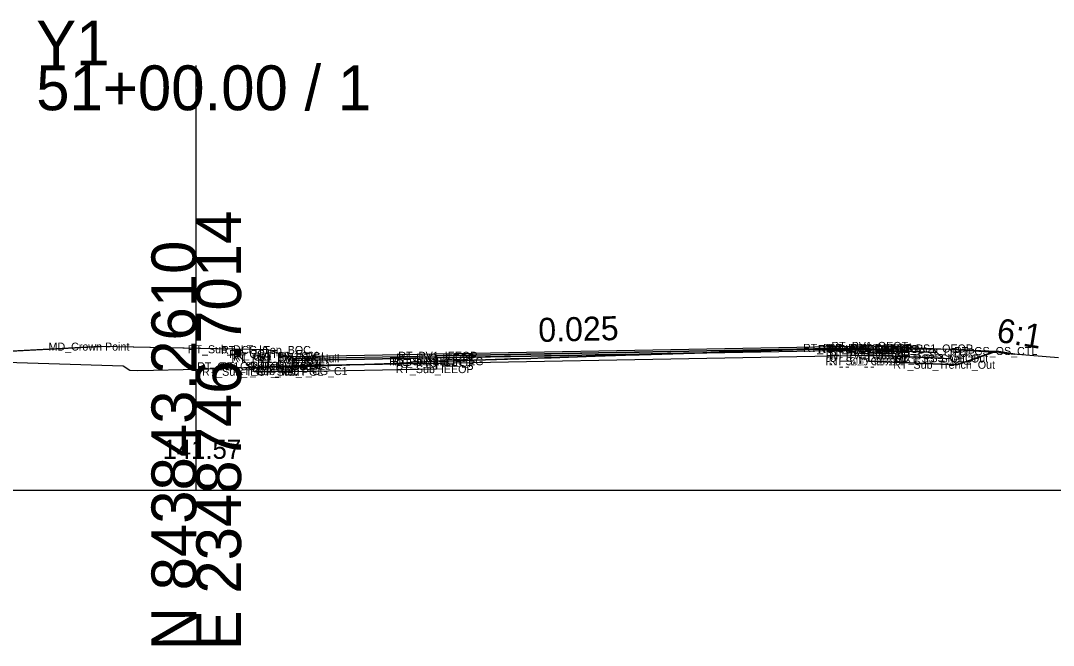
# Model space of a CAD drawing. Extents: x -26 to 2349090, y -10 to 844481.
# Drawn here: x 1139 to 1203.5, y 16490.3 to 16529.4 of the extents above; entities that cross this region are included whole.
import ezdxf

# ---------------------------------------------------------------- set-up
doc = ezdxf.new("R2010")
doc.units = 0
for name, color, linetype in [('Exist CMT Pavement', 7, 'Continuous'), ('Exist Cross Section Cell', 7, 'Continuous'), ('Exist XS Center Line Elevation Label', 7, 'Continuous'), ('Exist XS Ground Line', 7, 'Continuous'), ('Prop CMT Conc Surface', 7, 'Continuous'), ('Prop CMT Concrete Structures', 7, 'Continuous'), ('Prop CMT Pvmt Course 1', 7, 'Continuous'), ('Prop CMT Pvmt Course 1 CG', 7, 'Continuous'), ('Prop CMT Pvmt Course 1 Wedge', 7, 'Continuous'), ('Prop CMT Pvmt Course 2', 7, 'Continuous'), ('Prop CMT Pvmt Course 2 Wedge', 7, 'Continuous'), ('Prop CMT Pvmt Course 3', 7, 'Continuous'), ('Prop CMT Pvmt Surface', 7, 'Continuous'), ('Prop CMT Pvmt Surface Shoulder', 7, 'Continuous'), ('Prop CMT Pvmt Wedge Surface 1', 7, 'Continuous'), ('Prop CMT Pvmt Wedge Surface 2', 7, 'Continuous'), ('Prop CMT Pvmt Wedge Surface 3', 7, 'Continuous'), ('Prop CMT Shld Paved Course 1', 7, 'Continuous'), ('Prop CMT Shld Paved Course 2', 7, 'Continuous'), ('Prop CMT Shld Paved Course 3', 7, 'Continuous'), ('Prop CMT Slope Grass', 7, 'Continuous'), ('Prop CMT Subgrade Earthwork', 7, 'Continuous'), ('Prop XS Earthwork Shape', 7, 'Continuous'), ('Prop XS SE Text', 7, 'Continuous'), ('Prop XS Side Slope Text', 7, 'Continuous'), ('Scratch_Level_0', 7, 'Continuous')]:
    doc.layers.add(name, color=color, linetype=linetype)

msp = doc.modelspace()

# ---------------------------------------------------------------- linework, layer by layer
at = {"layer": 'Exist CMT Pavement'}
for p, q in [((1177.67, 16508.472), (1178.41, 16508.495)), ((1178.41, 16508.495), (1180.424, 16508.555)), ((1180.424, 16508.555), (1182.664, 16508.632)), ((1182.664, 16508.632), (1183.153, 16508.649)), ((1183.153, 16508.649), (1184.902, 16508.704)), ((1184.902, 16508.704), (1185.911, 16508.745)), ((1185.911, 16508.745), (1188.624, 16508.816)), ((1188.624, 16508.816), (1188.663, 16508.816)), ((1188.663, 16508.816), (1188.681, 16508.817)), ((1188.681, 16508.817), (1190.556, 16508.826)), ((1190.556, 16508.826), (1191.441, 16508.832)), ((1191.441, 16508.832), (1191.998, 16508.834)), ((1165.001, 16508.067), (1166.108, 16508.103)), ((1166.108, 16508.103), (1166.62, 16508.117)), ((1166.62, 16508.117), (1168.07, 16508.161)), ((1168.07, 16508.161), (1169.243, 16508.198)), ((1169.243, 16508.198), (1169.448, 16508.203)), ((1169.448, 16508.203), (1169.629, 16508.211)), ((1169.629, 16508.211), (1170.889, 16508.247)), ((1170.889, 16508.247), (1171.757, 16508.272)), ((1171.757, 16508.272), (1172.159, 16508.284)), ((1172.159, 16508.284), (1173.259, 16508.325)), ((1173.259, 16508.325), (1174.922, 16508.383)), ((1174.922, 16508.383), (1176.816, 16508.446)), ((1176.816, 16508.446), (1177.67, 16508.472))]:
    msp.add_line(p, q, dxfattribs=at)
at = {"layer": 'Exist Cross Section Cell'}
for p, q in [((1150, 16500), (1150, 16526.561)), ((1000, 16500), (1150, 16500)), ((1150, 16500), (1300, 16500))]:
    msp.add_line(p, q, dxfattribs=at)
at = {"layer": 'Exist XS Ground Line'}
msp.add_lwpolyline([(1135.459, 16508.084), (1145.443, 16507.772), (1145.852, 16507.511), (1146.316, 16507.489), (1147.334, 16507.506), (1149.183, 16507.543), (1150.096, 16507.57), (1153.053, 16507.671), (1155.6, 16507.728), (1156.437, 16507.748), (1157.536, 16507.771), (1158.394, 16507.801), (1159.082, 16507.827), (1161.125, 16507.905), (1162.341, 16507.955), (1163.894, 16508.029), (1164.221, 16508.042), (1164.965, 16508.066), (1166.108, 16508.103), (1166.62, 16508.117), (1168.07, 16508.161), (1169.448, 16508.203), (1170.889, 16508.247), (1171.757, 16508.272), (1172.159, 16508.284), (1173.258, 16508.325), (1174.922, 16508.383), (1176.816, 16508.446), (1177.67, 16508.472), (1178.41, 16508.495), (1180.424, 16508.555), (1182.664, 16508.632), (1183.153, 16508.649), (1184.902, 16508.704), (1185.911, 16508.745), (1188.681, 16508.817), (1190.556, 16508.826), (1191.441, 16508.832), (1193.129, 16508.839), (1193.505, 16508.84), (1194.047, 16508.852), (1194.533, 16508.854), (1197.341, 16508.818), (1200.031, 16508.605), (1203.856, 16508.303)], dxfattribs=at)
at = {"layer": 'Prop CMT Conc Surface'}
for p, q in [((1155.249, 16508.523), (1154.49, 16508.773)), ((1155.25, 16508.356), (1155.249, 16508.523)), ((1156, 16508.37), (1155.25, 16508.356))]:
    msp.add_line(p, q, dxfattribs=at)
at = {"layer": 'Prop CMT Concrete Structures'}
for p, q in [((1155.249, 16508.523), (1154.49, 16508.773)), ((1154.49, 16508.773), (1154.49, 16507.759)), ((1155.25, 16508.356), (1155.249, 16508.523)), ((1156, 16508.37), (1155.25, 16508.356)), ((1156, 16507.787), (1156, 16508.37)), ((1154.49, 16507.759), (1156, 16507.787))]:
    msp.add_line(p, q, dxfattribs=at)
at = {"layer": 'Prop CMT Pvmt Course 1'}
for p, q in [((1156, 16508.37), (1192, 16509.027)), ((1192, 16508.902), (1165, 16508.409)), ((1192, 16509.027), (1192, 16508.777)), ((1192, 16508.777), (1192, 16508.902)), ((1192, 16508.777), (1192, 16508.777)), ((1156, 16508.12), (1156, 16508.37)), ((1165, 16508.284), (1156, 16508.12)), ((1165, 16508.409), (1165, 16508.284))]:
    msp.add_line(p, q, dxfattribs=at)
at = {"layer": 'Prop CMT Pvmt Course 1 CG'}
for p, q in [((1153.99, 16507.75), (1153.65, 16507.41)), ((1153.65, 16507.41), (1156, 16507.453)), ((1156, 16507.787), (1153.99, 16507.75)), ((1156, 16507.453), (1156, 16507.787))]:
    msp.add_line(p, q, dxfattribs=at)
at = {"layer": 'Prop CMT Pvmt Course 1 Wedge'}
for p, q in [((1169.243, 16508.487), (1169.448, 16508.491)), ((1169.448, 16508.491), (1169.629, 16508.494)), ((1169.629, 16508.494), (1170.889, 16508.517)), ((1170.889, 16508.517), (1171.757, 16508.533)), ((1171.757, 16508.533), (1172.159, 16508.54)), ((1172.159, 16508.54), (1173.259, 16508.56)), ((1173.259, 16508.56), (1174.922, 16508.591)), ((1174.922, 16508.591), (1176.816, 16508.625)), ((1176.816, 16508.5), (1174.922, 16508.466)), ((1176.816, 16508.625), (1177.67, 16508.641)), ((1177.67, 16508.516), (1176.816, 16508.5)), ((1177.67, 16508.641), (1178.41, 16508.654)), ((1178.41, 16508.529), (1177.67, 16508.516)), ((1178.41, 16508.654), (1180.424, 16508.691)), ((1180.424, 16508.566), (1178.41, 16508.529)), ((1180.424, 16508.691), (1182.664, 16508.732)), ((1181.115, 16508.579), (1180.424, 16508.566)), ((1182.664, 16508.632), (1181.115, 16508.579)), ((1182.664, 16508.732), (1183.153, 16508.741)), ((1183.153, 16508.649), (1182.664, 16508.632)), ((1183.153, 16508.741), (1184.902, 16508.773)), ((1184.902, 16508.704), (1183.153, 16508.649)), ((1184.902, 16508.773), (1185.911, 16508.791)), ((1185.911, 16508.745), (1184.902, 16508.704)), ((1185.911, 16508.791), (1188.624, 16508.841)), ((1188.624, 16508.816), (1185.911, 16508.745)), ((1188.624, 16508.841), (1188.663, 16508.841)), ((1188.663, 16508.816), (1188.624, 16508.816)), ((1188.663, 16508.841), (1188.681, 16508.842)), ((1188.681, 16508.817), (1188.663, 16508.816)), ((1188.681, 16508.842), (1190.556, 16508.876)), ((1190.556, 16508.826), (1188.681, 16508.817)), ((1190.556, 16508.876), (1191.441, 16508.892)), ((1191.441, 16508.832), (1190.556, 16508.826)), ((1191.441, 16508.892), (1192, 16508.902)), ((1192, 16508.834), (1191.441, 16508.832)), ((1192, 16508.902), (1192, 16508.834)), ((1165, 16508.409), (1166.108, 16508.43)), ((1165, 16508.284), (1165, 16508.409)), ((1166.108, 16508.305), (1165, 16508.284)), ((1166.108, 16508.43), (1166.62, 16508.439)), ((1166.62, 16508.314), (1166.108, 16508.305)), ((1166.62, 16508.439), (1168.07, 16508.465)), ((1168.07, 16508.34), (1166.62, 16508.314)), ((1168.07, 16508.465), (1169.243, 16508.487)), ((1169.243, 16508.362), (1168.07, 16508.34)), ((1169.448, 16508.366), (1169.243, 16508.362)), ((1169.629, 16508.369), (1169.448, 16508.366)), ((1170.889, 16508.392), (1169.629, 16508.369)), ((1171.757, 16508.408), (1170.889, 16508.392)), ((1172.159, 16508.415), (1171.757, 16508.408)), ((1173.259, 16508.435), (1172.159, 16508.415)), ((1174.922, 16508.466), (1173.259, 16508.435))]:
    msp.add_line(p, q, dxfattribs=at)
at = {"layer": 'Prop CMT Pvmt Course 2'}
for p, q in [((1192, 16508.444), (1192, 16508.777)), ((1192, 16508.777), (1192, 16508.777)), ((1192, 16508.777), (1192, 16508.444)), ((1156, 16508.12), (1165, 16508.284)), ((1156, 16507.787), (1156, 16508.12)), ((1165, 16507.951), (1156, 16507.787)), ((1165, 16508.284), (1165, 16507.951)), ((1192, 16508.444), (1192, 16508.444))]:
    msp.add_line(p, q, dxfattribs=at)
at = {"layer": 'Prop CMT Pvmt Course 2 Wedge'}
for p, q in [((1174.922, 16508.466), (1176.816, 16508.5)), ((1176.816, 16508.5), (1177.67, 16508.516)), ((1177.67, 16508.516), (1178.41, 16508.529)), ((1178.41, 16508.495), (1177.67, 16508.472)), ((1178.41, 16508.529), (1180.424, 16508.566)), ((1180.424, 16508.555), (1178.41, 16508.495)), ((1180.424, 16508.566), (1181.115, 16508.579)), ((1181.115, 16508.579), (1180.424, 16508.555)), ((1165, 16508.284), (1166.108, 16508.305)), ((1165, 16508.067), (1165, 16508.284)), ((1166.108, 16508.103), (1165, 16508.067)), ((1166.108, 16508.305), (1166.62, 16508.314)), ((1166.62, 16508.117), (1166.108, 16508.103)), ((1166.62, 16508.314), (1168.07, 16508.34)), ((1168.07, 16508.161), (1166.62, 16508.117)), ((1168.07, 16508.34), (1169.243, 16508.362)), ((1169.243, 16508.198), (1168.07, 16508.161)), ((1169.243, 16508.362), (1169.448, 16508.366)), ((1169.448, 16508.203), (1169.243, 16508.198)), ((1169.448, 16508.366), (1169.629, 16508.369)), ((1169.629, 16508.211), (1169.448, 16508.203)), ((1169.629, 16508.369), (1170.889, 16508.392)), ((1170.889, 16508.247), (1169.629, 16508.211)), ((1170.889, 16508.392), (1171.757, 16508.408)), ((1171.757, 16508.272), (1170.889, 16508.247)), ((1171.757, 16508.408), (1172.159, 16508.415)), ((1172.159, 16508.284), (1171.757, 16508.272)), ((1172.159, 16508.415), (1173.259, 16508.435)), ((1173.259, 16508.325), (1172.159, 16508.284)), ((1173.259, 16508.435), (1174.922, 16508.466)), ((1174.922, 16508.383), (1173.259, 16508.325)), ((1176.816, 16508.446), (1174.922, 16508.383)), ((1177.67, 16508.472), (1176.816, 16508.446))]:
    msp.add_line(p, q, dxfattribs=at)
at = {"layer": 'Prop CMT Pvmt Course 3'}
for p, q in [((1156, 16507.787), (1165, 16507.951)), ((1165, 16507.951), (1165, 16507.576)), ((1192, 16508.444), (1192, 16508.444)), ((1192, 16508.444), (1192, 16508.069)), ((1192, 16508.069), (1192, 16508.444)), ((1192, 16508.069), (1192, 16508.069)), ((1156, 16507.412), (1156, 16507.787)), ((1165, 16507.576), (1156, 16507.412))]:
    msp.add_line(p, q, dxfattribs=at)
at = {"layer": 'Prop CMT Pvmt Surface'}
msp.add_line((1156, 16508.37), (1192, 16509.027), dxfattribs=at)
at = {"layer": 'Prop CMT Pvmt Surface Shoulder'}
msp.add_line((1192, 16509.027), (1196, 16508.867), dxfattribs=at)
at = {"layer": 'Prop CMT Pvmt Wedge Surface 1'}
for p, q in [((1165, 16508.409), (1192, 16508.902)), ((1192, 16508.902), (1192, 16509.027)), ((1192, 16508.902), (1192, 16508.902)), ((1156, 16508.245), (1165, 16508.409)), ((1156, 16508.37), (1156, 16508.245))]:
    msp.add_line(p, q, dxfattribs=at)
at = {"layer": 'Prop CMT Pvmt Wedge Surface 2'}
for p, q in [((1156, 16508.12), (1192, 16508.777)), ((1192, 16508.777), (1192, 16509.027)), ((1156, 16508.37), (1156, 16508.12))]:
    msp.add_line(p, q, dxfattribs=at)
at = {"layer": 'Prop CMT Pvmt Wedge Surface 3'}
for p, q in [((1192, 16508.444), (1192, 16509.027)), ((1156, 16507.787), (1192, 16508.444)), ((1156, 16508.37), (1156, 16507.787))]:
    msp.add_line(p, q, dxfattribs=at)
at = {"layer": 'Prop CMT Shld Paved Course 1'}
for p, q in [((1155.249, 16508.523), (1155.25, 16508.356)), ((1192, 16509.027), (1196, 16508.867)), ((1192, 16508.777), (1192, 16509.027)), ((1196.26, 16508.607), (1192, 16508.777)), ((1196, 16508.867), (1196.26, 16508.607))]:
    msp.add_line(p, q, dxfattribs=at)
at = {"layer": 'Prop CMT Shld Paved Course 2'}
for p, q in [((1192, 16508.777), (1196.26, 16508.607)), ((1192, 16508.444), (1192, 16508.777)), ((1196.26, 16508.607), (1196.608, 16508.26)), ((1196.608, 16508.26), (1192, 16508.444))]:
    msp.add_line(p, q, dxfattribs=at)
at = {"layer": 'Prop CMT Shld Paved Course 3'}
for p, q in [((1192, 16508.444), (1196.608, 16508.26)), ((1192, 16508.069), (1192, 16508.444)), ((1197.498, 16507.849), (1192, 16508.069)), ((1196.608, 16508.26), (1197.108, 16508.24)), ((1197.108, 16508.24), (1197.498, 16507.849))]:
    msp.add_line(p, q, dxfattribs=at)
at = {"layer": 'Prop CMT Slope Grass'}
for p, q in [((1133.51, 16508.441), (1144, 16508.983)), ((1154.49, 16508.773), (1144, 16508.983)), ((1196, 16508.867), (1200, 16508.707)), ((1200, 16508.707), (1201.14, 16508.517))]:
    msp.add_line(p, q, dxfattribs=at)
at = {"layer": 'Prop CMT Subgrade Earthwork'}
for p, q in [((1152.243, 16508.818), (1153.65, 16507.41)), ((1192, 16508.069), (1191.998, 16508.834)), ((1197.498, 16507.849), (1200, 16508.707)), ((1165, 16507.576), (1165.001, 16508.067)), ((1192, 16508.069), (1197.498, 16507.849)), ((1192, 16508.069), (1192, 16508.069)), ((1156, 16507.453), (1153.65, 16507.41)), ((1165, 16507.576), (1156, 16507.412)), ((1156, 16507.412), (1156, 16507.453))]:
    msp.add_line(p, q, dxfattribs=at)
at = {"layer": 'Prop XS Earthwork Shape'}
for points in [[(1146.316, 16507.489), (1147.334, 16507.506), (1149.183, 16507.543), (1150.096, 16507.57), (1153.053, 16507.671), (1153.383, 16507.678), (1152.243, 16508.818), (1144, 16508.983), (1135.67, 16508.553), (1135.209, 16508.092), (1135.459, 16508.084), (1145.443, 16507.772), (1145.852, 16507.511)], [(1191.998, 16508.834), (1193.129, 16508.839), (1193.505, 16508.84), (1194.047, 16508.852), (1194.533, 16508.854), (1197.202, 16508.819), (1197.439, 16508.81), (1199.763, 16508.626), (1197.498, 16507.849), (1192, 16508.069)], [(1197.341, 16508.818), (1197.439, 16508.81), (1197.202, 16508.819)], [(1200.031, 16508.605), (1201.14, 16508.517), (1200, 16508.707), (1199.763, 16508.626)], [(1163.894, 16508.029), (1164.221, 16508.042), (1164.965, 16508.066), (1165.001, 16508.067), (1165, 16507.576), (1156, 16507.412), (1156, 16507.453), (1153.65, 16507.41), (1153.383, 16507.678), (1155.6, 16507.728), (1156.437, 16507.748), (1157.536, 16507.771), (1158.394, 16507.801), (1159.082, 16507.827), (1161.125, 16507.905), (1162.341, 16507.955)], [(1169.243, 16508.198), (1169.448, 16508.203), (1168.07, 16508.161)], [(1169.629, 16508.211), (1170.889, 16508.247), (1169.448, 16508.203)]]:
    msp.add_lwpolyline(points, close=True, dxfattribs=at)

# ---------------------------------------------------------------- texts
at = {"layer": 'Exist Cross Section Cell'}
for s, p in [('Y1', (1140, 16526.561)), ('51+00.00 / 1', (1140, 16523.761))]:
    msp.add_text(s, height=2.8, dxfattribs=at).set_placement(p)
for s, p in [('E 2348746.7014', (1152.8, 16490)), ('N 843843.2610', (1150, 16490))]:
    msp.add_text(s, height=2.8, rotation=90, dxfattribs=at).set_placement(p)
at = {"layer": 'Exist XS Center Line Elevation Label'}
msp.add_text('141.57', height=1.2, dxfattribs=at).set_placement((1147.893, 16501.967))
at = {"layer": 'Prop XS SE Text'}
msp.add_text('0.025', height=1.5, rotation=1.4321, dxfattribs=at).set_placement((1171.38, 16509.271))
at = {"layer": 'Prop XS Side Slope Text'}
msp.add_text('6:1', height=1.5, rotation=350.53768, dxfattribs=at).set_placement((1199.932, 16509.301))
at = {"layer": 'Scratch_Level_0'}
for s, p in [('MD_Crown Point', (1140.768, 16508.733)), ('RT_PV1_OEOT_Overlay', (1187.898, 16508.652)), ('RT_PV1_OEEOP', (1189.457, 16508.652)), ('RT_PV1_OEOT', (1189.673, 16508.777)), ('RT_Sub_DLT_In', (1149.467, 16508.568)), ('RT_CG_Top_BOC', (1151.549, 16508.523)), ('RT_CG_Top_Face', (1152.052, 16508.273)), ('RT_PV1_Overlay_Null', (1152.205, 16507.995)), ('RT_CG_Top_Gut', (1152.297, 16508.106)), ('RT_PV1_PGL', (1153.933, 16508.12)), ('RT_PV2_IEEOP', (1162.476, 16508.034)), ('RT_PV1_IEEOP', (1162.618, 16508.159)), ('RT_Sub Tie Out', (1188.821, 16508.584)), ('RT_PV_OEEOP_EG', (1188.872, 16508.584)), ('RT_PV2_OEEOP', (1189.315, 16508.527)), ('RT_PV3_OEEOP', (1189.315, 16508.194)), ('RT_PV2_OEOT', (1189.531, 16508.527)), ('RT_PV3_OEOT', (1189.531, 16508.194)), ('RT_PS3_Shelf_Out', (1193.592, 16507.99)), ('RT_PS1_OEOP', (1193.689, 16508.617)), ('RT_PS2_OEOP', (1193.808, 16508.357)), ('RT_PS3_OEOP', (1194.155, 16508.01)), ('RT_GS_OS_CTL', (1197.331, 16508.457)), ('RT_CG1_Shelf_In_Med', (1150.049, 16507.5)), ('RT_CG_Bot_BOC1', (1151.474, 16507.509)), ('RT_CG_Bot_IE1', (1153.394, 16507.537)), ('RT_PV2_PGL', (1153.791, 16507.87)), ('RT_PV3_PGL', (1153.791, 16507.537)), ('RT_PV_IEEOP_EG', (1162.037, 16507.817)), ('RT_Sub Tie In', (1162.23, 16507.817)), ('RT_Sub_IEEOP', (1162.453, 16507.326)), ('RT_PV3_IEEOP', (1162.476, 16507.701)), ('RT_Sub_OEEOP', (1189.291, 16507.819)), ('RT_Sub_OEOT', (1189.508, 16507.819)), ('RT_Sub_Trench_Out', (1193.538, 16507.599)), ('RT_Sub_IEOP_Med', (1150.355, 16507.16)), ('RT_Sub_IEOT_CG_C1', (1152.468, 16507.203)), ('RT_Sub_PGL', (1153.768, 16507.162))]:
    msp.add_text(s, height=0.5, dxfattribs=at).set_placement(p)

doc.saveas('drawing.dxf')
